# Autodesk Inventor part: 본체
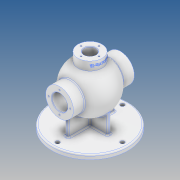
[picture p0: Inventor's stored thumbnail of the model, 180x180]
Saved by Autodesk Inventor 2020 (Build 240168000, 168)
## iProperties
Created: 2020-08
Part Number: 본체
Material: 알루미늄 6061
Document SubType Name: Modeling
Designer: EZDESIGN
Density: 2.7 g/cm^3
Appearance: 알루미늄 - 평지
Mass: 1752.49 g
Surface Area: 1343.01 cm^2
Volume: 649.072 cm^3
Author: EZDESIGN
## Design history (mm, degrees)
sketch "스케치1"
  geometry: C1 r 85 at (0, 0); 1 further point
  constraints: 1 centre point, 1 coincident
  dimensions: "d0" = 170 diameter of C1
extrude "돌출1" new body sketch "스케치1" distance "d1" = 10; taper "d2" = 0 deg
sketch "스케치2"
  geometry: L1 (85, 68)-(85, -68); L2 (0, -85)-(0, 85) reference; A1 r 53 centre (85, 0) between (85, -53) and (85, 53); 2 further points
  constraints: 2 end point, 2 point on circle, 2 point on line, 1 centre point, 1 coincident, 1 horizontal alignment, 1 midpoint, 1 vertical
  dimensions: "d3" = 136 distance of L1.start L1.end; "d4" = 85 distance between parallel lines of L2 L1; "d5" = 106 diameter of A1
revolve "회전1" sketch "스케치2" stored, may be unused: angle "d6" = 90 deg
sketch "스케치3"
  geometry: L1 (85, 68)-(85, -68); L2 (85, 68)-(116, 68); L3 (116, 68)-(116, 42.988); 4 further points
  constraints: 6 end point, 1 coincident, 1 horizontal, 1 midpoint, 1 perpendicular, 1 vertical, 1 vertical alignment, 2 other
  dimensions: "d7" = 136 distance of L1.start L1.end; "d8" = 62 diameter of L3 L1
revolve "회전2" sketch "스케치3" stored, may be unused: angle "d9" = 90 deg
node "작업 평면2"
sketch "스케치4"
  geometry: C1 r 27 at (0, 0); 1 further point
  constraints: 1 centre point, 1 coincident
  dimensions: "d11" = 54 diameter of C1
extrude "돌출2" join sketch "스케치4" distance "d12" = 50; taper "d13" = 0 deg
sketch "스케치5"
  geometry: L1 (54, 68)-(54, 42.988) reference; L2 (54, -42.988)-(54, -68) reference; L3 (10, -85)-(10, 85) reference; L4 (54, 52)-(10, 52); L5 (67.304, -52)-(10, -52); L6 (54, 52)-(67.304, 52); L7 (67.304, 52)-(67.304, -52); A1 r 53 centre (85, 0) between (54, 42.988) and (116, 42.988) reference; 3 further points
  constraints: 8 end point, 3 perpendicular, 3 point on line, 1 horizontal
  dimensions: "d14" = 104 distance between parallel lines of L4 L5; "d15" = 52 distance from line of point (0, 0) L5; "d16" = 13.30408 distance of L4.start L6.end
extrude "돌출3" join sketch "스케치5" stored distance "d17" = 8; taper "d18" = 0 deg
sketch "스케치6"
  geometry: L1 (85, 10)-(-85, 10) reference; L2 (43, 54.016)-(43, 10); A1 r 53 centre (0, 85) between (-27, 130.607) and (27, 130.607) reference; 1 further point
  constraints: 2 end point, 1 perpendicular, 1 point on circle, 1 point on line
  dimensions: "d20" = 43 distance from line of point (0, 0) L2
feature "리브1" sketch "스케치6" dims "d21" = 1, "d22" = 8, "d23" = 0, "d24" = 0, "d25" = 1, "d26" = 1
sketch "스케치7"
  geometry: L1 (85, -43)-(85, 43); A1 r 53 centre (85, 0) between (116, -42.988) and (116, 42.988) reference; A2 r 43 centre (85, 0) between (85, -43) and (85, 43); 2 further points
  constraints: 2 coincident, 2 end point, 2 point on circle, 1 centre point, 1 midpoint, 1 vertical, 1 vertical alignment
  dimensions: "d27" = 86 distance of L1.start L1.end
revolve "회전3" sketch "스케치7" stored, may be unused: angle "d28" = 90 deg
sketch "스케치8"
  geometry: L1 (54, -68)-(116, -68) reference; L2 (54, 68)-(116, 68) reference; L3 (85, -68)-(85, 68); L4 (102.5, -68)-(102.5, -52); L5 (102.5, -52)-(103.5, -52); L6 (103.5, -52)-(103.5, -50.25); L7 (103.5, -50.25)-(102.5, -50.25); L8 (102.5, -50.25)-(102.5, 68); 1 further point
  constraints: 12 end point, 4 point on line, 3 perpendicular, 2 midpoint, 1 vertical
  dimensions: "d29" = 16 distance of L4.start L4.end; "d30" = 35 diameter of L4 L3; "d31" = 37 diameter of L6 L3; "d32" = 1.75 distance of L5.end L6.end
revolve "회전4" sketch "스케치8" stored, may be unused: angle "d33" = 90 deg
sketch "스케치9"
  geometry: C1 r 13 at (0, 0); 1 further point
  constraints: 1 centre point, 1 coincident
  dimensions: "d34" = 26 diameter of C1
extrude "돌출4" cut sketch "스케치9" distance "d35" = 40; taper "d36" = 0 deg
sketch "스케치10"
  geometry: C1 r 17.5 at (0, 0) reference; 5 further points
  constraints: 1 vertical alignment, 5 other
  dimensions: "d37" = 24 distance of C1.centre point (0, 24); "d40" = 360 deg dimension on C1.centre point (0, 24) (derived)
hole "구멍1" sketch "스케치10" at (0, 24), (-24, 0), (0, -24), (24, 0) diameter "d42" = 3.242; stored, may be unused: countersink angle "d46" = 90 deg, drill point angle "d48" = 118 deg; dims "d43" = 12, "d44" = 4, "d45" = 2, "d47" = 15
sketch "스케치11"
  geometry: C1 r 17.5 at (0, 0) reference; 5 further points
  constraints: 1 vertical alignment, 5 other
  dimensions: "d49" = 24 distance of C1.centre point (0, 24); "d52" = 360 deg dimension on C1.centre point (0, 24) (derived)
hole "구멍2" sketch "스케치11" at (0, 24), (-24, 0), (0, -24), (24, 0) diameter "d54" = 3.242; stored, may be unused: countersink angle "d58" = 90 deg, drill point angle "d60" = 118 deg; dims "d55" = 12, "d56" = 4, "d57" = 2, "d59" = 15
sketch "스케치12"
  geometry: C1 r 4.5 at (0, 72.5); C2 r 4.5 at (-72.5, 0); C3 r 4.5 at (0, -72.5); C4 r 4.5 at (72.5, 0); 1 further point
  constraints: 4 centre point, 1 vertical alignment, 9 other
  dimensions: "d61" = 9 diameter of C1; "d62" = 72.5 distance of point (0, 0) C1.centre; "d65" = 360 deg dimension on point (0, 0) C1.centre (derived)
extrude "돌출5" cut sketch "스케치12" distance "d67" = 40; taper "d68" = 0 deg
fillet "모깎기1" dims "d69" = 3
fillet "모깎기2" dims "d70" = 3
fillet "모깎기3" dims "d71" = 3
fillet "모깎기4" dims "d72" = 3
fillet "모깎기5" dims "d73" = 3
chamfer "모따기1" distance "d74" = 1; stored, may be unused: second distance "d75" = 2, angle "d76" = 45 deg
chamfer "모따기2" distance "d77" = 1; stored, may be unused: second distance "d78" = 2, angle "d79" = 45 deg
chamfer "모따기3" distance "d80" = 1; stored, may be unused: second distance "d81" = 2, angle "d82" = 45 deg
sketch "스케치13"
  geometry: 5 further points
  constraints: 1 horizontal alignment, 5 other
  dimensions: "d83" = 20 distance of point (0, 0) point (20, 0); "d86" = 360 deg dimension on point (0, 0) point (20, 0) (derived)
hole "구멍3" sketch "스케치13" at (20, 0), (0, 20), (-20, 0), (0, -20) diameter "d88" = 3.242; stored, may be unused: countersink angle "d92" = 90 deg, drill point angle "d94" = 118 deg; dims "d89" = 12, "d90" = 4, "d91" = 2, "d93" = 15
node "작업 평면3"
sketch "스케치14"
  geometry: L1 (150, -27)-(150, 27) reference; 2 further points
  constraints: 1 horizontal alignment, 1 other
  dimensions: "d96" = 9 distance from line of L1 point (141, 0)
feature "엠보싱1" sketch "스케치14" dims "d1" = 10, "d97" = 0.5, "d98" = 0
node "솔리드1"
mirror "미러1"
mirror "미러2"
node "작업 평면1"
feature "A9D066F2-1C7D-4E18-AEED-F7BC21143FA4" dims "d54" = 3.242, "d55" = 12, "d56" = 4, "d57" = 2, "d58" = 90 deg, "d59" = 15, "d60" = 118 deg
other parameters: "d95" = 110.5
